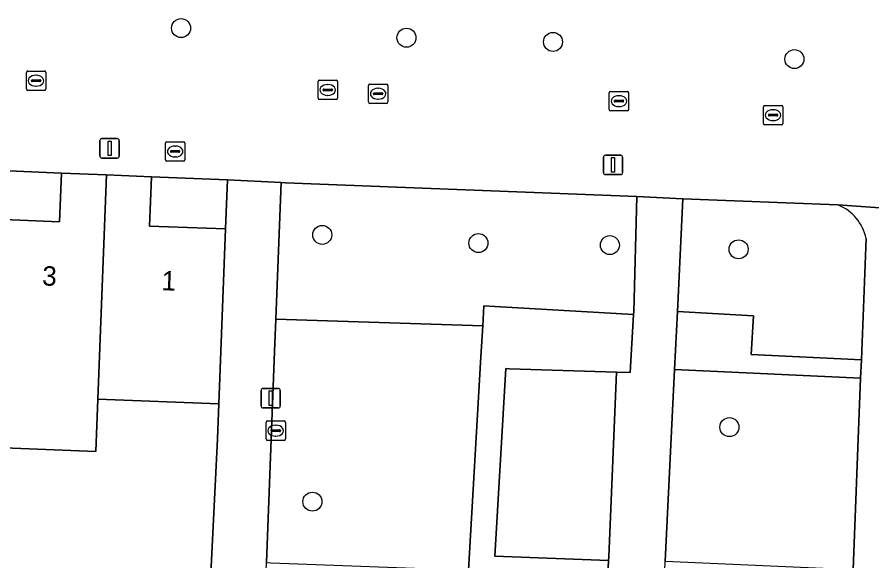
# Model space of a CAD drawing. Extents: x 160786 to 161429, y 386828 to 387485.
# Drawn here: x 161260.64 to 161304.65, y 387290.07 to 387318.08 of the extents above; entities that cross this region are included whole.
import ezdxf

# ---------------------------------------------------------------- set-up
doc = ezdxf.new("R2010")
doc.units = 0
for name, color, linetype in [('IMGEO_Boom', 7, 'Continuous'), ('IMGEO_Brandkraan', 7, 'Continuous'), ('IMGEO_Erf', 7, 'Continuous'), ('IMGEO_Groenvoorziening', 7, 'Continuous'), ('IMGEO_Kolk', 7, 'Continuous'), ('IMGEO_Lichtmast', 7, 'Continuous'), ('IMGEO_Muur', 7, 'Continuous'), ('IMGEO_Pand', 7, 'Continuous'), ('IMGEO_Pand_nummerreeks', 7, 'Continuous'), ('IMGEO_Rijbaan_lokaal_open', 7, 'Continuous'), ('IMGEO_Rioolput', 7, 'Continuous'), ('IMGEO_Voetpad_open', 7, 'Continuous')]:
    doc.layers.add(name, color=color, linetype=linetype)

msp = doc.modelspace()

# ---------------------------------------------------------------- linework, layer by layer
at = {"layer": 'IMGEO_Boom'}
for centre in [(161269.081, 387317.508), (161280.689, 387317.015), (161288.233, 387316.797), (161300.661, 387315.912), (161276.353, 387306.861), (161284.392, 387306.44), (161291.161, 387306.334), (161297.789, 387306.118), (161297.313, 387296.96), (161275.845, 387293.124)]:
    msp.add_circle(centre, 0.489, dxfattribs=at)
at = {"layer": 'IMGEO_Brandkraan'}
for p, q in [((161268.279, 387310.73), (161268.279, 387311.582)), ((161268.354, 387311.656), (161269.206, 387311.656)), ((161268.767, 387311.436), (161268.792, 387311.436)), ((161269.28, 387311.582), (161269.28, 387310.73)), ((161268.538, 387311.15), (161268.538, 387311.162)), ((161268.976, 387311.113), (161268.578, 387311.113)), ((161268.581, 387311.199), (161268.979, 387311.199)), ((161269.022, 387311.162), (161269.022, 387311.15)), ((161269.206, 387310.656), (161268.354, 387310.656)), ((161268.79, 387310.876), (161268.765, 387310.876))]:
    msp.add_line(p, q, dxfattribs=at)
for points in [[(161268.279, 387310.73), (161268.279, 387311.582)], [(161268.354, 387311.656), (161269.206, 387311.656)], [(161269.28, 387311.582), (161269.28, 387310.73)], [(161269.206, 387310.656), (161268.354, 387310.656)]]:
    msp.add_lwpolyline(points, dxfattribs=at)
for centre, radius, start, end in [((161268.356, 387311.58), 0.0765, 91.552, 178.448), ((161268.356, 387311.58), 0.0765, 91.552, 178.448), ((161269.204, 387311.58), 0.0765, 1.552, 88.448), ((161269.204, 387311.58), 0.0765, 1.552, 88.448), ((161268.578, 387311.159), 0.0403, 85.8775, 175.7526), ((161268.575, 387311.149), 0.0366, 178.938, 274.7102), ((161268.979, 387311.156), 0.043, 264.8664, 352.4533), ((161268.983, 387311.161), 0.0386, 1.7309, 96.639), ((161268.356, 387310.732), 0.0765, 181.552, 268.448), ((161268.356, 387310.732), 0.0765, 181.552, 268.448), ((161269.204, 387310.732), 0.0765, 271.552, 358.448), ((161269.204, 387310.732), 0.0765, 271.552, 358.448)]:
    msp.add_arc(centre, radius, start, end, dxfattribs=at)
for centre, major_axis, ratio, start_param, end_param in [((161268.766, 387311.156), (-0.387, 0.002), 0.722429, 4.712389, 7.853982), ((161268.791, 387311.156), (-0.39, 0.002), 0.717154, 1.570796, 4.712389)]:
    msp.add_ellipse(centre, major_axis=major_axis, ratio=ratio, start_param=start_param, end_param=end_param, dxfattribs=at)
at = {"layer": 'IMGEO_Erf'}
for points in [[(161255.544, 387310.358), (161255.445, 387307.829), (161259.138, 387307.685), (161262.831, 387307.54), (161262.928, 387310.038)], [(161267.563, 387309.857), (161267.463, 387307.317), (161271.371, 387307.164), (161271.47, 387309.704)]]:
    msp.add_lwpolyline(points, close=True, dxfattribs=at)
msp.add_lwpolyline([(161270.534, 387287.689), (161270.955, 387296.361), (161271.019, 387298.166), (161264.797, 387298.409), (161264.691, 387295.71), (161258.678, 387295.946), (161258.784, 387298.645), (161252.762, 387298.88), (161246.766, 387299.115), (161240.766, 387299.349), (161234.793, 387299.583), (161234.642, 387295.726), (161228.676, 387295.96), (161228.827, 387299.816)], dxfattribs=at)
at = {"layer": 'IMGEO_Groenvoorziening'}
for points in [[(161292.547, 387308.838), (161274.466, 387309.538), (161274.237, 387309.551), (161273.964, 387302.526), (161284.613, 387302.181), (161284.672, 387303.21), (161285.23, 387303.178), (161292.385, 387302.761), (161292.393, 387302.899)], [(161284.613, 387302.181), (161273.964, 387302.526), (161273.9, 387300.864), (161273.479, 387289.987), (161273.705, 387289.978), (161283.889, 387289.598), (161284.521, 387300.577)], [(161291.497, 387299.789), (161285.994, 387299.97), (161285.804, 387299.976), (161285.238, 387290.308), (161291.094, 387290.089), (161291.102, 387290.29)], [(161304.073, 387299.482), (161294.493, 387299.929), (161294.014, 387290.055), (161303.694, 387289.628)]]:
    msp.add_lwpolyline(points, close=True, dxfattribs=at)
msp.add_lwpolyline([(161302.906, 387308.403), (161294.919, 387308.722), (161294.638, 387302.923), (161298.55, 387302.688), (161298.442, 387300.708), (161304.109, 387300.435), (161304.349, 387306.671)], dxfattribs=at)
msp.add_arc((161302.035, 387306.211), 2.359, 11.2562, 68.3419, dxfattribs=at)
at = {"layer": 'IMGEO_Kolk'}
for p, q in [((161278.728, 387313.704), (161278.728, 387314.556)), ((161278.803, 387314.63), (161279.655, 387314.63)), ((161279.216, 387314.41), (161279.241, 387314.41)), ((161279.729, 387314.556), (161279.729, 387313.704)), ((161278.987, 387314.124), (161278.987, 387314.136)), ((161279.425, 387314.087), (161279.027, 387314.087)), ((161279.03, 387314.173), (161279.428, 387314.173)), ((161279.471, 387314.136), (161279.471, 387314.124)), ((161279.655, 387313.63), (161278.803, 387313.63)), ((161279.239, 387313.85), (161279.214, 387313.85)), ((161299.137, 387313.527), (161299.989, 387313.527)), ((161299.062, 387312.601), (161299.062, 387313.453)), ((161299.55, 387313.307), (161299.575, 387313.307)), ((161300.063, 387313.453), (161300.063, 387312.601)), ((161299.321, 387313.021), (161299.321, 387313.033)), ((161299.759, 387312.984), (161299.361, 387312.984)), ((161299.364, 387313.07), (161299.762, 387313.07)), ((161299.573, 387312.747), (161299.548, 387312.747)), ((161299.805, 387313.033), (161299.805, 387313.021)), ((161299.989, 387312.527), (161299.137, 387312.527)), ((161273.532, 387297.278), (161274.384, 387297.278)), ((161273.457, 387296.352), (161273.457, 387297.204)), ((161273.759, 387296.821), (161274.157, 387296.821)), ((161273.945, 387297.058), (161273.97, 387297.058)), ((161274.458, 387297.204), (161274.458, 387296.352)), ((161273.716, 387296.772), (161273.716, 387296.784)), ((161274.154, 387296.735), (161273.756, 387296.735)), ((161273.968, 387296.498), (161273.943, 387296.498)), ((161274.2, 387296.784), (161274.2, 387296.772)), ((161274.384, 387296.278), (161273.532, 387296.278))]:
    msp.add_line(p, q, dxfattribs=at)
for points in [[(161278.728, 387313.704), (161278.728, 387314.556)], [(161278.803, 387314.63), (161279.655, 387314.63)], [(161279.729, 387314.556), (161279.729, 387313.704)], [(161279.655, 387313.63), (161278.803, 387313.63)], [(161299.137, 387313.527), (161299.989, 387313.527)], [(161299.062, 387312.601), (161299.062, 387313.453)], [(161300.063, 387313.453), (161300.063, 387312.601)], [(161299.989, 387312.527), (161299.137, 387312.527)], [(161273.532, 387297.278), (161274.384, 387297.278)], [(161273.457, 387296.352), (161273.457, 387297.204)], [(161274.458, 387297.204), (161274.458, 387296.352)], [(161274.384, 387296.278), (161273.532, 387296.278)]]:
    msp.add_lwpolyline(points, dxfattribs=at)
for centre, radius, start, end in [((161278.805, 387314.554), 0.0765, 91.552, 178.448), ((161278.805, 387314.554), 0.0765, 91.552, 178.448), ((161279.653, 387314.554), 0.0765, 1.552, 88.448), ((161279.653, 387314.554), 0.0765, 1.552, 88.448), ((161279.027, 387314.133), 0.0403, 85.8775, 175.7526), ((161279.024, 387314.123), 0.0366, 178.938, 274.7102), ((161279.428, 387314.13), 0.043, 264.8664, 352.4533), ((161279.432, 387314.135), 0.0386, 1.7309, 96.639), ((161278.805, 387313.706), 0.0765, 181.552, 268.448), ((161278.805, 387313.706), 0.0765, 181.552, 268.448), ((161279.653, 387313.706), 0.0765, 271.552, 358.448), ((161279.653, 387313.706), 0.0765, 271.552, 358.448), ((161299.139, 387313.451), 0.0765, 91.552, 178.448), ((161299.139, 387313.451), 0.0765, 91.552, 178.448), ((161299.987, 387313.451), 0.0765, 1.552, 88.448), ((161299.987, 387313.451), 0.0765, 1.552, 88.448), ((161299.361, 387313.03), 0.0403, 85.8775, 175.7526), ((161299.358, 387313.02), 0.0366, 178.938, 274.7102), ((161299.762, 387313.027), 0.043, 264.8664, 352.4533), ((161299.766, 387313.032), 0.0386, 1.7309, 96.639), ((161299.139, 387312.603), 0.0765, 181.552, 268.448), ((161299.139, 387312.603), 0.0765, 181.552, 268.448), ((161299.987, 387312.603), 0.0765, 271.552, 358.448), ((161299.987, 387312.603), 0.0765, 271.552, 358.448), ((161273.534, 387297.202), 0.0765, 91.552, 178.448), ((161273.534, 387297.202), 0.0765, 91.552, 178.448), ((161274.382, 387297.202), 0.0765, 1.552, 88.448), ((161274.382, 387297.202), 0.0765, 1.552, 88.448), ((161273.756, 387296.781), 0.0403, 85.8775, 175.7526), ((161274.161, 387296.783), 0.0386, 1.7309, 96.639), ((161273.753, 387296.771), 0.0366, 178.938, 274.7102), ((161274.157, 387296.778), 0.043, 264.8664, 352.4533), ((161273.534, 387296.354), 0.0765, 181.552, 268.448), ((161273.534, 387296.354), 0.0765, 181.552, 268.448), ((161274.382, 387296.354), 0.0765, 271.552, 358.448), ((161274.382, 387296.354), 0.0765, 271.552, 358.448)]:
    msp.add_arc(centre, radius, start, end, dxfattribs=at)
for centre, major_axis, ratio, start_param, end_param in [((161279.215, 387314.13), (-0.387, 0.002), 0.722429, 4.712389, 7.853982), ((161279.24, 387314.13), (-0.39, 0.002), 0.717154, 1.570796, 4.712389), ((161299.549, 387313.027), (-0.387, 0.002), 0.722429, 4.712389, 7.853982), ((161299.574, 387313.027), (-0.39, 0.002), 0.717154, 1.570796, 4.712389), ((161273.944, 387296.778), (-0.387, 0.002), 0.722429, 4.712389, 7.853982), ((161273.969, 387296.778), (-0.39, 0.002), 0.717154, 1.570796, 4.712389)]:
    msp.add_ellipse(centre, major_axis=major_axis, ratio=ratio, start_param=start_param, end_param=end_param, dxfattribs=at)
at = {"layer": 'IMGEO_Lichtmast'}
for p, q in [((161265.007, 387311.817), (161265.797, 387311.817)), ((161265.797, 387311.817), (161265.007, 387311.817)), ((161264.907, 387310.917), (161264.907, 387311.717)), ((161264.907, 387311.717), (161264.907, 387310.917)), ((161265.897, 387311.717), (161265.897, 387310.917)), ((161265.897, 387310.917), (161265.897, 387311.717)), ((161290.929, 387310.963), (161291.719, 387310.963)), ((161291.719, 387310.963), (161290.929, 387310.963)), ((161265.797, 387310.817), (161265.007, 387310.817)), ((161265.007, 387310.817), (161265.797, 387310.817)), ((161290.829, 387310.063), (161290.829, 387310.863)), ((161290.829, 387310.863), (161290.829, 387310.063)), ((161291.819, 387310.863), (161291.819, 387310.063)), ((161291.819, 387310.063), (161291.819, 387310.863)), ((161291.719, 387309.963), (161290.929, 387309.963)), ((161290.929, 387309.963), (161291.719, 387309.963)), ((161273.199, 387298.05), (161273.199, 387298.85)), ((161273.199, 387298.85), (161273.199, 387298.05)), ((161273.299, 387298.95), (161274.089, 387298.95)), ((161274.089, 387298.95), (161273.299, 387298.95)), ((161274.189, 387298.85), (161274.189, 387298.05)), ((161274.189, 387298.05), (161274.189, 387298.85)), ((161274.089, 387297.95), (161273.299, 387297.95)), ((161273.299, 387297.95), (161274.089, 387297.95))]:
    msp.add_line(p, q, dxfattribs=at)
for points in [[(161265.327, 387311.692), (161265.477, 387311.692), (161265.477, 387310.942), (161265.327, 387310.942), (161265.327, 387311.692)], [(161291.249, 387310.838), (161291.399, 387310.838), (161291.399, 387310.088), (161291.249, 387310.088), (161291.249, 387310.838)], [(161273.619, 387298.825), (161273.769, 387298.825), (161273.769, 387298.075), (161273.619, 387298.075), (161273.619, 387298.825)]]:
    msp.add_lwpolyline(points, dxfattribs=at)
for centre, start, end in [((161265.007, 387311.717), 90, 180), ((161265.007, 387311.717), 90, 180), ((161265.797, 387311.717), 0, 90), ((161265.797, 387311.717), 360, 90), ((161265.007, 387310.917), 180, 270), ((161265.007, 387310.917), 180, 270), ((161265.797, 387310.917), 270, 0), ((161265.797, 387310.917), 270, 0), ((161290.929, 387310.863), 90, 180), ((161290.929, 387310.863), 90, 180), ((161291.719, 387310.863), 0, 90), ((161291.719, 387310.863), 360, 90), ((161290.929, 387310.063), 180, 270), ((161290.929, 387310.063), 180, 270), ((161291.719, 387310.063), 270, 0), ((161291.719, 387310.063), 270, 0), ((161273.299, 387298.85), 90, 180), ((161273.299, 387298.85), 90, 180), ((161274.089, 387298.85), 0, 90), ((161274.089, 387298.85), 360, 90), ((161273.299, 387298.05), 180, 270), ((161273.299, 387298.05), 180, 270), ((161274.089, 387298.05), 270, 0), ((161274.089, 387298.05), 270, 0)]:
    msp.add_arc(centre, 0.1, start, end, dxfattribs=at)
at = {"layer": 'IMGEO_Muur'}
msp.add_lwpolyline([(161271.019, 387298.166), (161270.955, 387296.361)], dxfattribs=at)
at = {"layer": 'IMGEO_Pand'}
for points in [[(161265.248, 387309.947), (161262.928, 387310.038), (161262.831, 387307.54), (161259.138, 387307.685), (161258.784, 387298.645), (161258.678, 387295.946), (161264.691, 387295.71), (161264.797, 387298.409)], [(161265.248, 387309.947), (161264.797, 387298.409), (161271.019, 387298.166), (161271.371, 387307.164), (161267.463, 387307.317), (161267.563, 387309.857)]]:
    msp.add_lwpolyline(points, close=True, dxfattribs=at)
at = {"layer": 'IMGEO_Rijbaan_lokaal_open'}
msp.add_lwpolyline([(161255.544, 387310.358), (161262.928, 387310.038), (161265.248, 387309.947), (161267.563, 387309.857), (161271.47, 387309.704), (161274.237, 387309.551), (161274.466, 387309.538), (161292.547, 387308.838), (161294.919, 387308.722), (161302.906, 387308.403), (161309.167, 387307.955), (161310.147, 387307.885), (161321.14, 387307.403), (161324.756, 387307.244), (161327.414, 387307.234), (161327.498, 387308.874), (161327.639, 387314.293), (161327.794, 387318.092)], dxfattribs=at)
at = {"layer": 'IMGEO_Rioolput'}
for p, q in [((161261.191, 387315.3), (161262.043, 387315.3)), ((161261.116, 387314.374), (161261.116, 387315.226)), ((161261.418, 387314.843), (161261.816, 387314.843)), ((161261.604, 387315.08), (161261.629, 387315.08)), ((161262.117, 387315.226), (161262.117, 387314.374)), ((161261.375, 387314.794), (161261.375, 387314.806)), ((161261.813, 387314.757), (161261.415, 387314.757)), ((161261.627, 387314.52), (161261.602, 387314.52)), ((161261.859, 387314.806), (161261.859, 387314.794)), ((161276.133, 387313.899), (161276.133, 387314.751)), ((161276.208, 387314.825), (161277.06, 387314.825)), ((161276.621, 387314.605), (161276.646, 387314.605)), ((161277.134, 387314.751), (161277.134, 387313.899)), ((161262.043, 387314.3), (161261.191, 387314.3)), ((161276.392, 387314.319), (161276.392, 387314.331)), ((161276.83, 387314.282), (161276.432, 387314.282)), ((161276.435, 387314.368), (161276.833, 387314.368)), ((161276.644, 387314.045), (161276.619, 387314.045)), ((161276.876, 387314.331), (161276.876, 387314.319)), ((161291.127, 387313.322), (161291.127, 387314.174)), ((161291.202, 387314.248), (161292.054, 387314.248)), ((161291.615, 387314.028), (161291.64, 387314.028)), ((161292.128, 387314.174), (161292.128, 387313.322)), ((161277.06, 387313.825), (161276.208, 387313.825)), ((161291.386, 387313.742), (161291.386, 387313.754)), ((161291.824, 387313.705), (161291.426, 387313.705)), ((161291.429, 387313.791), (161291.827, 387313.791)), ((161291.87, 387313.754), (161291.87, 387313.742)), ((161292.054, 387313.248), (161291.202, 387313.248)), ((161291.638, 387313.468), (161291.613, 387313.468))]:
    msp.add_line(p, q, dxfattribs=at)
for points in [[(161261.191, 387315.3), (161262.043, 387315.3)], [(161261.116, 387314.374), (161261.116, 387315.226)], [(161262.117, 387315.226), (161262.117, 387314.374)], [(161276.133, 387313.899), (161276.133, 387314.751)], [(161276.208, 387314.825), (161277.06, 387314.825)], [(161277.134, 387314.751), (161277.134, 387313.899)], [(161262.043, 387314.3), (161261.191, 387314.3)], [(161291.127, 387313.322), (161291.127, 387314.174)], [(161291.202, 387314.248), (161292.054, 387314.248)], [(161292.128, 387314.174), (161292.128, 387313.322)], [(161277.06, 387313.825), (161276.208, 387313.825)], [(161292.054, 387313.248), (161291.202, 387313.248)]]:
    msp.add_lwpolyline(points, dxfattribs=at)
for centre, radius, start, end in [((161261.193, 387315.224), 0.0765, 91.552, 178.448), ((161261.193, 387315.224), 0.0765, 91.552, 178.448), ((161262.041, 387315.224), 0.0765, 1.552, 88.448), ((161262.041, 387315.224), 0.0765, 1.552, 88.448), ((161261.415, 387314.803), 0.0403, 85.8775, 175.7526), ((161261.82, 387314.805), 0.0386, 1.7309, 96.639), ((161261.412, 387314.793), 0.0366, 178.938, 274.7102), ((161261.816, 387314.8), 0.043, 264.8664, 352.4533), ((161276.21, 387314.749), 0.0765, 91.552, 178.448), ((161276.21, 387314.749), 0.0765, 91.552, 178.448), ((161277.058, 387314.749), 0.0765, 1.552, 88.448), ((161277.058, 387314.749), 0.0765, 1.552, 88.448), ((161261.193, 387314.376), 0.0765, 181.552, 268.448), ((161261.193, 387314.376), 0.0765, 181.552, 268.448), ((161262.041, 387314.376), 0.0765, 271.552, 358.448), ((161262.041, 387314.376), 0.0765, 271.552, 358.448), ((161276.432, 387314.328), 0.0403, 85.8775, 175.7526), ((161276.429, 387314.318), 0.0366, 178.938, 274.7102), ((161276.833, 387314.325), 0.043, 264.8664, 352.4533), ((161276.837, 387314.33), 0.0386, 1.7309, 96.639), ((161291.204, 387314.172), 0.0765, 91.552, 178.448), ((161291.204, 387314.172), 0.0765, 91.552, 178.448), ((161292.052, 387314.172), 0.0765, 1.552, 88.448), ((161292.052, 387314.172), 0.0765, 1.552, 88.448), ((161276.21, 387313.901), 0.0765, 181.552, 268.448), ((161276.21, 387313.901), 0.0765, 181.552, 268.448), ((161277.058, 387313.901), 0.0765, 271.552, 358.448), ((161277.058, 387313.901), 0.0765, 271.552, 358.448), ((161291.426, 387313.751), 0.0403, 85.8775, 175.7526), ((161291.423, 387313.741), 0.0366, 178.938, 274.7102), ((161291.827, 387313.748), 0.043, 264.8664, 352.4533), ((161291.831, 387313.753), 0.0386, 1.7309, 96.639), ((161291.204, 387313.324), 0.0765, 181.552, 268.448), ((161291.204, 387313.324), 0.0765, 181.552, 268.448), ((161292.052, 387313.324), 0.0765, 271.552, 358.448), ((161292.052, 387313.324), 0.0765, 271.552, 358.448)]:
    msp.add_arc(centre, radius, start, end, dxfattribs=at)
for centre, major_axis, ratio, start_param, end_param in [((161261.603, 387314.8), (-0.387, 0.002), 0.722429, 4.712389, 7.853982), ((161261.628, 387314.8), (-0.39, 0.002), 0.717154, 1.570796, 4.712389), ((161276.62, 387314.325), (-0.387, 0.002), 0.722429, 4.712389, 7.853982), ((161276.645, 387314.325), (-0.39, 0.002), 0.717154, 1.570796, 4.712389), ((161291.614, 387313.748), (-0.387, 0.002), 0.722429, 4.712389, 7.853982), ((161291.639, 387313.748), (-0.39, 0.002), 0.717154, 1.570796, 4.712389)]:
    msp.add_ellipse(centre, major_axis=major_axis, ratio=ratio, start_param=start_param, end_param=end_param, dxfattribs=at)
at = {"layer": 'IMGEO_Voetpad_open'}
for points in [[(161270.807, 387220.973), (161272.761, 387271.438), (161273.121, 387280.725), (161273.325, 387286.006), (161273.479, 387289.987), (161273.9, 387300.864), (161273.964, 387302.526), (161274.237, 387309.551), (161271.47, 387309.704), (161271.371, 387307.164), (161271.019, 387298.166), (161270.955, 387296.361), (161270.534, 387287.689), (161270.377, 387282.829), (161270.21, 387278.628), (161269.921, 387271.505), (161269.755, 387267.338), (161269.563, 387262.328)], [(161293.967, 387289.091), (161294.014, 387290.055), (161294.493, 387299.929), (161294.638, 387302.923), (161294.919, 387308.722), (161292.547, 387308.838), (161292.393, 387302.899), (161292.385, 387302.761), (161292.211, 387299.766), (161291.497, 387299.789), (161291.102, 387290.29), (161291.094, 387290.089), (161291.062, 387289.307), (161290.851, 387284.241), (161290.84, 387283.965), (161276.444, 387284.522), (161275.775, 387284.563)], [(161309.167, 387307.955), (161302.906, 387308.403)], [(161304.349, 387306.671), (161304.109, 387300.435), (161304.073, 387299.482), (161303.694, 387289.628), (161303.658, 387288.686), (161303.381, 387281.452), (161303.343, 387280.473), (161303.222, 387277.308), (161303.203, 387276.825), (161302.955, 387270.497), (161302.945, 387270.254), (161300.754, 387214.371)]]:
    msp.add_lwpolyline(points, dxfattribs=at)
for points in [[(161292.385, 387302.761), (161285.23, 387303.178), (161284.672, 387303.21), (161284.613, 387302.181), (161284.521, 387300.577), (161283.889, 387289.598), (161284.434, 387289.578), (161291.062, 387289.307), (161291.094, 387290.089), (161285.238, 387290.308), (161285.804, 387299.976), (161285.994, 387299.97), (161291.497, 387299.789), (161292.211, 387299.766)], [(161298.55, 387302.688), (161294.638, 387302.923), (161294.493, 387299.929), (161304.073, 387299.482), (161304.109, 387300.435), (161298.442, 387300.708)]]:
    msp.add_lwpolyline(points, close=True, dxfattribs=at)
msp.add_arc((161302.035, 387306.211), 2.359, 11.2562, 68.3419, dxfattribs=at)

# ---------------------------------------------------------------- texts
at = {"layer": 'IMGEO_Pand_nummerreeks'}
for s, rotation, p in [('3', 357.7082, (161261.918, 387304.26)), ('1', 357.7066, (161268.063, 387304.014))]:
    msp.add_text(s, height=1, rotation=rotation, dxfattribs=at).set_placement(p)

doc.saveas('drawing.dxf')
